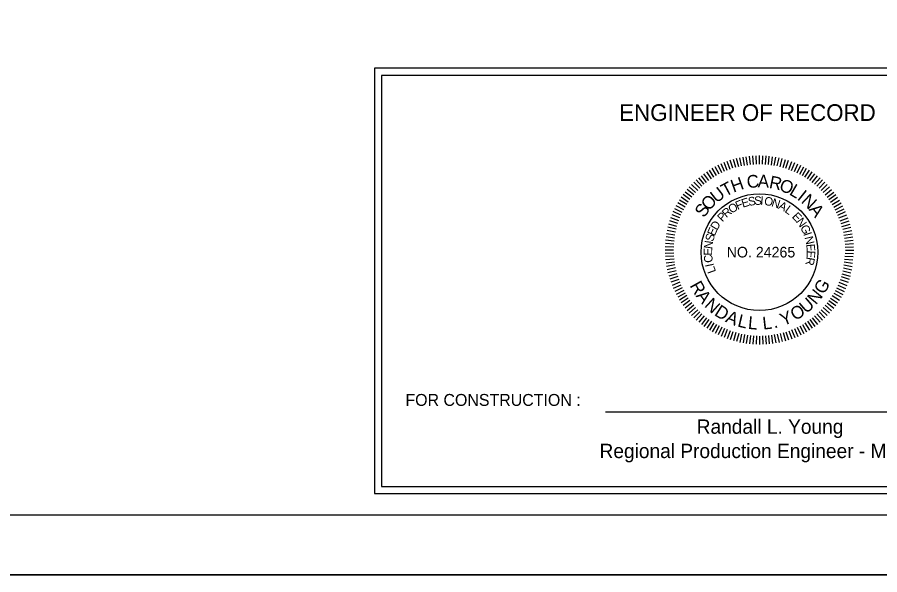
# Model space of a CAD drawing. Extents: x -796 to 2793, y -4650 to 4425.
# Drawn here: x 2234 to 2596, y 1000 to 1233.8 of the extents above; entities that cross this region are included whole.
import ezdxf

# ---------------------------------------------------------------- set-up
doc = ezdxf.new("R2010")
doc.units = 0
for name, color, linetype in [('RD_EX_Misc', 7, 'Continuous'), ('RD_HC_CL', 7, 'Continuous'), ('RD_HC_Data', 7, 'Continuous'), ('RD_HC_Data_Tic', 7, 'Continuous'), ('RD_SHT_Bndy', 7, 'Continuous')]:
    doc.layers.add(name, color=color, linetype=linetype)

msp = doc.modelspace()

# ---------------------------------------------------------------- linework, layer by layer
at = {"layer": 'RD_EX_Misc'}
for p, q in [((2531.98, 1169.54), (2530.65, 1172.84)), ((2531.98, 1169.54), (2530.65, 1172.84)), ((2533.16, 1169.99), (2531.94, 1173.33)), ((2533.16, 1169.99), (2531.94, 1173.33)), ((2534.33, 1170.44), (2533.23, 1173.83)), ((2534.33, 1170.44), (2533.23, 1173.83)), ((2535.55, 1170.77), (2534.57, 1174.18)), ((2535.55, 1170.77), (2534.57, 1174.18)), ((2536.76, 1171.09), (2535.9, 1174.54)), ((2536.76, 1171.09), (2535.9, 1174.54)), ((2537.98, 1171.42), (2537.24, 1174.9)), ((2537.98, 1171.42), (2537.24, 1174.9)), ((2539.22, 1171.61), (2538.6, 1175.12)), ((2539.22, 1171.61), (2538.6, 1175.12)), ((2540.46, 1171.81), (2539.97, 1175.33)), ((2540.46, 1171.81), (2539.97, 1175.33)), ((2541.7, 1172.01), (2541.33, 1175.55)), ((2541.7, 1172.01), (2541.33, 1175.55)), ((2542.96, 1172.07), (2542.71, 1175.62)), ((2542.96, 1172.07), (2542.71, 1175.62)), ((2544.21, 1172.14), (2544.09, 1175.69)), ((2544.21, 1172.14), (2544.09, 1175.69)), ((2545.47, 1172.2), (2545.47, 1175.76)), ((2545.47, 1172.2), (2545.47, 1175.76)), ((2546.73, 1172.14), (2546.85, 1175.69)), ((2546.73, 1172.14), (2546.85, 1175.69)), ((2547.98, 1172.07), (2548.23, 1175.62)), ((2547.98, 1172.07), (2548.23, 1175.62)), ((2549.24, 1172.01), (2549.61, 1175.55)), ((2549.24, 1172.01), (2549.61, 1175.55)), ((2550.48, 1171.81), (2550.98, 1175.33)), ((2550.48, 1171.81), (2550.98, 1175.33)), ((2551.72, 1171.61), (2552.34, 1175.12)), ((2551.72, 1171.61), (2552.34, 1175.12)), ((2552.96, 1171.42), (2553.71, 1174.9)), ((2552.96, 1171.42), (2553.71, 1174.9)), ((2552.96, 1171.42), (2553.71, 1174.9)), ((2554.18, 1171.09), (2555.04, 1174.54)), ((2554.18, 1171.09), (2555.04, 1174.54)), ((2554.18, 1171.09), (2555.04, 1174.54)), ((2555.39, 1170.77), (2556.37, 1174.18)), ((2555.39, 1170.77), (2556.37, 1174.18)), ((2555.39, 1170.77), (2556.37, 1174.18)), ((2556.61, 1170.44), (2557.71, 1173.83)), ((2556.61, 1170.44), (2557.71, 1173.83)), ((2556.61, 1170.44), (2557.71, 1173.83)), ((2557.78, 1169.99), (2559, 1173.33)), ((2557.78, 1169.99), (2559, 1173.33)), ((2557.78, 1169.99), (2559, 1173.33)), ((2558.96, 1169.54), (2560.29, 1172.84)), ((2558.96, 1169.54), (2560.29, 1172.84)), ((2558.96, 1169.54), (2560.29, 1172.84)), ((2526.39, 1166.69), (2524.51, 1169.71)), ((2526.39, 1166.69), (2524.51, 1169.71)), ((2527.45, 1167.38), (2525.67, 1170.46)), ((2527.45, 1167.38), (2525.67, 1170.46)), ((2528.57, 1167.95), (2526.9, 1171.09)), ((2528.57, 1167.95), (2526.9, 1171.09)), ((2529.69, 1168.52), (2528.13, 1171.71)), ((2529.69, 1168.52), (2528.13, 1171.71)), ((2530.81, 1169.09), (2529.36, 1172.34)), ((2530.81, 1169.09), (2529.36, 1172.34)), ((2560.13, 1169.09), (2561.58, 1172.34)), ((2560.13, 1169.09), (2561.58, 1172.34)), ((2560.13, 1169.09), (2561.58, 1172.34)), ((2561.25, 1168.52), (2562.81, 1171.71)), ((2561.25, 1168.52), (2562.81, 1171.71)), ((2561.25, 1168.52), (2562.81, 1171.71)), ((2562.37, 1167.95), (2564.04, 1171.09)), ((2562.37, 1167.95), (2564.04, 1171.09)), ((2562.37, 1167.95), (2564.04, 1171.09)), ((2563.49, 1167.38), (2565.27, 1170.46)), ((2563.49, 1167.38), (2565.27, 1170.46)), ((2563.49, 1167.38), (2565.27, 1170.46)), ((2564.55, 1166.69), (2566.43, 1169.71)), ((2564.55, 1166.69), (2566.43, 1169.71)), ((2564.55, 1166.69), (2566.43, 1169.71)), ((2521.35, 1162.95), (2518.97, 1165.59)), ((2521.35, 1162.95), (2518.97, 1165.59)), ((2522.33, 1163.74), (2520.04, 1166.46)), ((2522.33, 1163.74), (2520.04, 1166.46)), ((2523.31, 1164.53), (2521.12, 1167.33)), ((2523.31, 1164.53), (2521.12, 1167.33)), ((2524.28, 1165.32), (2522.19, 1168.2)), ((2524.28, 1165.32), (2522.19, 1168.2)), ((2525.34, 1166.01), (2523.35, 1168.95)), ((2525.34, 1166.01), (2523.35, 1168.95)), ((2565.6, 1166.01), (2567.59, 1168.95)), ((2565.6, 1166.01), (2567.59, 1168.95)), ((2565.6, 1166.01), (2567.59, 1168.95)), ((2566.66, 1165.32), (2568.75, 1168.2)), ((2566.66, 1165.32), (2568.75, 1168.2)), ((2566.66, 1165.32), (2568.75, 1168.2)), ((2567.64, 1164.53), (2569.82, 1167.33)), ((2567.64, 1164.53), (2569.82, 1167.33)), ((2567.64, 1164.53), (2569.82, 1167.33)), ((2568.61, 1163.74), (2570.9, 1166.46)), ((2568.61, 1163.74), (2570.9, 1166.46)), ((2568.61, 1163.74), (2570.9, 1166.46)), ((2569.59, 1162.95), (2571.97, 1165.59)), ((2569.59, 1162.95), (2571.97, 1165.59)), ((2569.59, 1162.95), (2571.97, 1165.59)), ((2518.68, 1160.28), (2516.04, 1162.66)), ((2518.68, 1160.28), (2516.04, 1162.66)), ((2519.57, 1161.17), (2517.02, 1163.64)), ((2519.57, 1161.17), (2517.02, 1163.64)), ((2520.46, 1162.06), (2517.99, 1164.61)), ((2520.46, 1162.06), (2517.99, 1164.61)), ((2570.48, 1162.06), (2572.95, 1164.61)), ((2570.48, 1162.06), (2572.95, 1164.61)), ((2570.48, 1162.06), (2572.95, 1164.61)), ((2571.37, 1161.17), (2573.93, 1163.64)), ((2571.37, 1161.17), (2573.93, 1163.64)), ((2571.37, 1161.17), (2573.93, 1163.64)), ((2572.26, 1160.28), (2574.9, 1162.66)), ((2572.26, 1160.28), (2574.9, 1162.66)), ((2572.26, 1160.28), (2574.9, 1162.66)), ((2515.62, 1156.29), (2512.68, 1158.28)), ((2515.62, 1156.29), (2512.68, 1158.28)), ((2516.31, 1157.35), (2513.43, 1159.44)), ((2516.31, 1157.35), (2513.43, 1159.44)), ((2517.1, 1158.32), (2514.3, 1160.51)), ((2517.1, 1158.32), (2514.3, 1160.51)), ((2517.89, 1159.3), (2515.17, 1161.59)), ((2517.89, 1159.3), (2515.17, 1161.59)), ((2573.05, 1159.3), (2575.77, 1161.59)), ((2573.05, 1159.3), (2575.77, 1161.59)), ((2573.05, 1159.3), (2575.77, 1161.59)), ((2573.84, 1158.32), (2576.64, 1160.51)), ((2573.84, 1158.32), (2576.64, 1160.51)), ((2573.84, 1158.32), (2576.64, 1160.51)), ((2574.63, 1157.35), (2577.51, 1159.44)), ((2574.63, 1157.35), (2577.51, 1159.44)), ((2574.63, 1157.35), (2577.51, 1159.44)), ((2575.32, 1156.29), (2578.26, 1158.28)), ((2575.32, 1156.29), (2578.26, 1158.28)), ((2575.32, 1156.29), (2578.26, 1158.28)), ((2513.68, 1153.06), (2510.54, 1154.73)), ((2513.68, 1153.06), (2510.54, 1154.73)), ((2514.25, 1154.18), (2511.17, 1155.96)), ((2514.25, 1154.18), (2511.17, 1155.96)), ((2514.94, 1155.24), (2511.92, 1157.12)), ((2514.94, 1155.24), (2511.92, 1157.12)), ((2576, 1155.24), (2579.02, 1157.12)), ((2576, 1155.24), (2579.02, 1157.12)), ((2576, 1155.24), (2579.02, 1157.12)), ((2576.69, 1154.18), (2579.77, 1155.96)), ((2576.69, 1154.18), (2579.77, 1155.96)), ((2576.69, 1154.18), (2579.77, 1155.96)), ((2577.26, 1153.06), (2580.4, 1154.73)), ((2577.26, 1153.06), (2580.4, 1154.73)), ((2577.26, 1153.06), (2580.4, 1154.73)), ((2512.54, 1150.82), (2509.29, 1152.27)), ((2512.54, 1150.82), (2509.29, 1152.27)), ((2513.11, 1151.94), (2509.92, 1153.5)), ((2513.11, 1151.94), (2509.92, 1153.5)), ((2577.83, 1151.94), (2581.02, 1153.5)), ((2577.83, 1151.94), (2581.02, 1153.5)), ((2577.83, 1151.94), (2581.02, 1153.5)), ((2578.4, 1150.82), (2581.65, 1152.27)), ((2578.4, 1150.82), (2581.65, 1152.27)), ((2578.4, 1150.82), (2581.65, 1152.27)), ((2511.19, 1147.3), (2507.8, 1148.4)), ((2511.19, 1147.3), (2507.8, 1148.4)), ((2511.64, 1148.47), (2508.3, 1149.69)), ((2511.64, 1148.47), (2508.3, 1149.69)), ((2512.09, 1149.65), (2508.79, 1150.98)), ((2512.09, 1149.65), (2508.79, 1150.98)), ((2578.85, 1149.65), (2582.15, 1150.98)), ((2578.85, 1149.65), (2582.15, 1150.98)), ((2578.85, 1149.65), (2582.15, 1150.98)), ((2579.3, 1148.47), (2582.64, 1149.69)), ((2579.3, 1148.47), (2582.64, 1149.69)), ((2579.3, 1148.47), (2582.64, 1149.69)), ((2579.75, 1147.3), (2583.14, 1148.4)), ((2579.75, 1147.3), (2583.14, 1148.4)), ((2579.75, 1147.3), (2583.14, 1148.4)), ((2510.21, 1143.65), (2506.73, 1144.39)), ((2510.21, 1143.65), (2506.73, 1144.39)), ((2510.54, 1144.87), (2507.09, 1145.73)), ((2510.54, 1144.87), (2507.09, 1145.73)), ((2510.86, 1146.08), (2507.45, 1147.06)), ((2510.86, 1146.08), (2507.45, 1147.06)), ((2580.08, 1146.08), (2583.5, 1147.06)), ((2580.08, 1146.08), (2583.5, 1147.06)), ((2580.08, 1146.08), (2583.5, 1147.06)), ((2580.4, 1144.87), (2583.85, 1145.73)), ((2580.4, 1144.87), (2583.85, 1145.73)), ((2580.4, 1144.87), (2583.85, 1145.73)), ((2580.73, 1143.65), (2584.21, 1144.39)), ((2580.73, 1143.65), (2584.21, 1144.39)), ((2580.73, 1143.65), (2584.21, 1144.39)), ((2509.62, 1139.93), (2506.08, 1140.3)), ((2509.62, 1139.93), (2506.08, 1140.3)), ((2509.82, 1141.17), (2506.3, 1141.67)), ((2509.82, 1141.17), (2506.3, 1141.67)), ((2510.02, 1142.41), (2506.52, 1143.03)), ((2510.02, 1142.41), (2506.52, 1143.03)), ((2580.92, 1142.41), (2584.43, 1143.03)), ((2580.92, 1142.41), (2584.43, 1143.03)), ((2580.92, 1142.41), (2584.43, 1143.03)), ((2581.12, 1141.17), (2584.64, 1141.67)), ((2581.12, 1141.17), (2584.64, 1141.67)), ((2581.12, 1141.17), (2584.64, 1141.67)), ((2581.32, 1139.93), (2584.86, 1140.3)), ((2581.32, 1139.93), (2584.86, 1140.3)), ((2581.32, 1139.93), (2584.86, 1140.3)), ((2509.49, 1137.42), (2505.94, 1137.54)), ((2509.49, 1137.42), (2505.94, 1137.54)), ((2509.56, 1138.67), (2506.01, 1138.92)), ((2509.56, 1138.67), (2506.01, 1138.92)), ((2581.38, 1138.67), (2584.93, 1138.92)), ((2581.38, 1138.67), (2584.93, 1138.92)), ((2581.38, 1138.67), (2584.93, 1138.92)), ((2581.45, 1137.42), (2585, 1137.54)), ((2581.45, 1137.42), (2585, 1137.54)), ((2581.45, 1137.42), (2585, 1137.54)), ((2509.43, 1136.16), (2505.87, 1136.16)), ((2509.43, 1136.16), (2505.87, 1136.16)), ((2509.49, 1134.9), (2505.94, 1134.78)), ((2509.49, 1134.9), (2505.94, 1134.78)), ((2509.56, 1133.65), (2506.01, 1133.4)), ((2509.56, 1133.65), (2506.01, 1133.4)), ((2581.25, 1133.66), (2584.79, 1133.41)), ((2581.25, 1133.66), (2584.79, 1133.41)), ((2581.38, 1134.91), (2584.93, 1134.78)), ((2581.38, 1134.91), (2584.93, 1134.78)), ((2581.52, 1136.16), (2585.08, 1136.16)), ((2581.52, 1136.16), (2585.08, 1136.16)), ((2581.52, 1136.16), (2585.08, 1136.16)), ((2509.62, 1132.39), (2506.08, 1132.02)), ((2509.62, 1132.39), (2506.08, 1132.02)), ((2509.82, 1131.15), (2506.3, 1130.65)), ((2509.82, 1131.15), (2506.3, 1130.65)), ((2510.02, 1129.91), (2506.52, 1129.29)), ((2510.02, 1129.91), (2506.52, 1129.29)), ((2580.86, 1129.92), (2584.36, 1129.3)), ((2580.86, 1129.92), (2584.36, 1129.3)), ((2580.99, 1131.17), (2584.5, 1130.67)), ((2580.99, 1131.17), (2584.5, 1130.67)), ((2581.12, 1132.41), (2584.64, 1132.04)), ((2581.12, 1132.41), (2584.64, 1132.04)), ((2510.21, 1128.67), (2506.73, 1127.93)), ((2510.21, 1128.67), (2506.73, 1127.93)), ((2510.54, 1127.45), (2507.09, 1126.59)), ((2510.54, 1127.45), (2507.09, 1126.59)), ((2510.86, 1126.24), (2507.45, 1125.26)), ((2510.86, 1126.24), (2507.45, 1125.26)), ((2580.08, 1126.24), (2583.5, 1125.26)), ((2580.08, 1126.24), (2583.5, 1125.26)), ((2580.4, 1127.45), (2583.85, 1126.59)), ((2580.4, 1127.45), (2583.85, 1126.59)), ((2580.73, 1128.67), (2584.21, 1127.93)), ((2580.73, 1128.67), (2584.21, 1127.93)), ((2511.19, 1125.02), (2507.8, 1123.92)), ((2511.64, 1123.85), (2508.3, 1122.63)), ((2511.64, 1123.85), (2508.3, 1122.63)), ((2512.09, 1122.67), (2508.79, 1121.34)), ((2512.09, 1122.67), (2508.79, 1121.34)), ((2578.85, 1122.67), (2582.15, 1121.34)), ((2578.85, 1122.67), (2582.15, 1121.34)), ((2579.3, 1123.85), (2582.64, 1122.63)), ((2579.3, 1123.85), (2582.64, 1122.63)), ((2579.75, 1125.02), (2583.14, 1123.92)), ((2579.75, 1125.02), (2583.14, 1123.92)), ((2512.54, 1121.5), (2509.29, 1120.05)), ((2512.54, 1121.5), (2509.29, 1120.05)), ((2513.11, 1120.38), (2509.92, 1118.82)), ((2513.11, 1120.38), (2509.92, 1118.82)), ((2513.68, 1119.26), (2510.54, 1117.59)), ((2513.68, 1119.26), (2510.54, 1117.59)), ((2577.26, 1119.26), (2580.4, 1117.59)), ((2577.26, 1119.26), (2580.4, 1117.59)), ((2577.83, 1120.38), (2581.02, 1118.82)), ((2577.83, 1120.38), (2581.02, 1118.82)), ((2578.4, 1121.5), (2581.65, 1120.05)), ((2578.4, 1121.5), (2581.65, 1120.05)), ((2514.25, 1118.14), (2511.17, 1116.36)), ((2514.25, 1118.14), (2511.17, 1116.36)), ((2514.94, 1117.08), (2511.92, 1115.2)), ((2514.94, 1117.08), (2511.92, 1115.2)), ((2515.62, 1116.03), (2512.68, 1114.04)), ((2515.62, 1116.03), (2512.68, 1114.04)), ((2516.31, 1114.97), (2513.43, 1112.88)), ((2516.31, 1114.97), (2513.43, 1112.88)), ((2574.63, 1114.97), (2577.51, 1112.88)), ((2574.63, 1114.97), (2577.51, 1112.88)), ((2575.32, 1116.03), (2578.26, 1114.04)), ((2575.32, 1116.03), (2578.26, 1114.04)), ((2576, 1117.08), (2579.02, 1115.2)), ((2576, 1117.08), (2579.02, 1115.2)), ((2576.69, 1118.14), (2579.77, 1116.36)), ((2576.69, 1118.14), (2579.77, 1116.36)), ((2517.1, 1114), (2514.3, 1111.81)), ((2517.1, 1114), (2514.3, 1111.81)), ((2517.89, 1113.02), (2515.17, 1110.73)), ((2517.89, 1113.02), (2515.17, 1110.73)), ((2518.68, 1112.04), (2516.04, 1109.66)), ((2518.68, 1112.04), (2516.04, 1109.66)), ((2572.26, 1112.04), (2574.9, 1109.66)), ((2572.26, 1112.04), (2574.9, 1109.66)), ((2573.05, 1113.02), (2575.77, 1110.73)), ((2573.05, 1113.02), (2575.77, 1110.73)), ((2573.84, 1114), (2576.64, 1111.81)), ((2573.84, 1114), (2576.64, 1111.81)), ((2519.57, 1111.15), (2517.02, 1108.68)), ((2519.57, 1111.15), (2517.02, 1108.68)), ((2520.46, 1110.26), (2517.99, 1107.71)), ((2520.46, 1110.26), (2517.99, 1107.71)), ((2521.35, 1109.37), (2518.97, 1106.73)), ((2521.35, 1109.37), (2518.97, 1106.73)), ((2522.33, 1108.58), (2520.04, 1105.86)), ((2522.33, 1108.58), (2520.04, 1105.86)), ((2523.31, 1107.79), (2521.12, 1104.99)), ((2523.31, 1107.79), (2521.12, 1104.99)), ((2567.64, 1107.79), (2569.82, 1104.99)), ((2567.64, 1107.79), (2569.82, 1104.99)), ((2568.61, 1108.58), (2570.9, 1105.86)), ((2568.61, 1108.58), (2570.9, 1105.86)), ((2569.59, 1109.37), (2571.97, 1106.73)), ((2570.48, 1110.26), (2572.95, 1107.71)), ((2570.48, 1110.26), (2572.95, 1107.71)), ((2571.37, 1111.15), (2573.93, 1108.68)), ((2571.37, 1111.15), (2573.93, 1108.68)), ((2524.28, 1107), (2522.19, 1104.12)), ((2524.28, 1107), (2522.19, 1104.12)), ((2525.34, 1106.31), (2523.35, 1103.37)), ((2525.34, 1106.31), (2523.35, 1103.37)), ((2526.39, 1105.63), (2524.51, 1102.61)), ((2526.39, 1105.63), (2524.51, 1102.61)), ((2527.45, 1104.94), (2525.67, 1101.86)), ((2527.45, 1104.94), (2525.67, 1101.86)), ((2528.57, 1104.37), (2526.9, 1101.23)), ((2528.57, 1104.37), (2526.9, 1101.23)), ((2562.37, 1104.37), (2564.04, 1101.23)), ((2562.37, 1104.37), (2564.04, 1101.23)), ((2563.49, 1104.94), (2565.27, 1101.86)), ((2563.49, 1104.94), (2565.27, 1101.86)), ((2564.55, 1105.63), (2566.43, 1102.61)), ((2564.55, 1105.63), (2566.43, 1102.61)), ((2565.6, 1106.31), (2567.59, 1103.37)), ((2565.6, 1106.31), (2567.59, 1103.37)), ((2566.66, 1107), (2568.75, 1104.12)), ((2566.66, 1107), (2568.75, 1104.12)), ((2529.69, 1103.8), (2528.13, 1100.61)), ((2529.69, 1103.8), (2528.13, 1100.61)), ((2530.81, 1103.23), (2529.36, 1099.98)), ((2530.81, 1103.23), (2529.36, 1099.98)), ((2531.98, 1102.78), (2530.65, 1099.48)), ((2531.98, 1102.78), (2530.65, 1099.48)), ((2533.16, 1102.33), (2531.94, 1098.99)), ((2533.16, 1102.33), (2531.94, 1098.99)), ((2534.33, 1101.88), (2533.23, 1098.49)), ((2534.33, 1101.88), (2533.23, 1098.49)), ((2535.55, 1101.55), (2534.57, 1098.14)), ((2535.55, 1101.55), (2534.57, 1098.14)), ((2536.76, 1101.23), (2535.9, 1097.78)), ((2536.76, 1101.23), (2535.9, 1097.78)), ((2537.98, 1100.9), (2537.24, 1097.42)), ((2537.98, 1100.9), (2537.24, 1097.42)), ((2539.22, 1100.71), (2538.6, 1097.2)), ((2539.22, 1100.71), (2538.6, 1097.2)), ((2540.46, 1100.51), (2539.97, 1096.99)), ((2540.46, 1100.51), (2539.97, 1096.99)), ((2550.48, 1100.51), (2550.98, 1096.99)), ((2550.48, 1100.51), (2550.98, 1096.99)), ((2551.72, 1100.71), (2552.34, 1097.2)), ((2551.72, 1100.71), (2552.34, 1097.2)), ((2552.96, 1100.9), (2553.71, 1097.42)), ((2552.96, 1100.9), (2553.71, 1097.42)), ((2554.18, 1101.23), (2555.04, 1097.78)), ((2554.18, 1101.23), (2555.04, 1097.78)), ((2555.39, 1101.55), (2556.37, 1098.14)), ((2555.39, 1101.55), (2556.37, 1098.14)), ((2556.61, 1101.88), (2557.71, 1098.49)), ((2556.61, 1101.88), (2557.71, 1098.49)), ((2557.78, 1102.33), (2559, 1098.99)), ((2557.78, 1102.33), (2559, 1098.99)), ((2558.96, 1102.78), (2560.29, 1099.48)), ((2558.96, 1102.78), (2560.29, 1099.48)), ((2560.13, 1103.23), (2561.58, 1099.98)), ((2560.13, 1103.23), (2561.58, 1099.98)), ((2561.25, 1103.8), (2562.81, 1100.61)), ((2561.25, 1103.8), (2562.81, 1100.61)), ((2541.7, 1100.31), (2541.33, 1096.77)), ((2541.7, 1100.31), (2541.33, 1096.77)), ((2542.96, 1100.25), (2542.71, 1096.7)), ((2542.96, 1100.25), (2542.71, 1096.7)), ((2544.21, 1100.18), (2544.09, 1096.63)), ((2544.21, 1100.18), (2544.09, 1096.63)), ((2545.47, 1100.11), (2545.47, 1096.55)), ((2545.47, 1100.11), (2545.47, 1096.55)), ((2546.73, 1100.18), (2546.85, 1096.63)), ((2546.73, 1100.18), (2546.85, 1096.63)), ((2547.98, 1100.25), (2548.23, 1096.7)), ((2547.98, 1100.25), (2548.23, 1096.7)), ((2549.24, 1100.31), (2549.61, 1096.77)), ((2549.24, 1100.31), (2549.61, 1096.77))]:
    msp.add_line(p, q, dxfattribs=at)
msp.add_circle((2545.47, 1135.28), 24.48, dxfattribs=at)
at = {"layer": 'RD_HC_CL'}
msp.add_lwpolyline([(984.13, 2100), (2780.13, 2100), (2780.13, 1000), (984.13, 1000)], close=True, dxfattribs=at)
at = {"layer": 'RD_HC_Data'}
for p, q in [((2480.88, 1068.27), (2619.52, 1068.27)), ((2760, 1000), (1000, 1000)), ((1000, 1000), (2759.98, 1000))]:
    msp.add_line(p, q, dxfattribs=at)
for points in [[(1079.63, 2075.05), (2755.13, 2075.05), (2755.13, 1025), (1079.63, 1025)], [(2383.87, 1034.06), (2702.13, 1034.06), (2702.13, 1212.42), (2383.87, 1212.42)], [(2386.87, 1037.06), (2699.13, 1037.06), (2699.13, 1209.42), (2386.87, 1209.42)]]:
    msp.add_lwpolyline(points, close=True, dxfattribs=at)

# ---------------------------------------------------------------- texts
at = {"layer": 'RD_EX_Misc'}
for s, height, rotation, p in [('H', 5.34, 19.9102, (2534.57, 1160.2)), ('C', 5.34, 6.8832, (2540.46, 1162.02)), ('A', 5.34, 357.9448, (2544.68, 1162.47)), ('R', 5.34, 348.267, (2549.26, 1162.22)), ('O', 5.34, 339.3286, (2553.4, 1161.3)), ('U', 5.34, 37.7726, (2527.45, 1155.66)), ('T', 5.34, 28.0947, (2531.13, 1158.4)), ('L', 5.34, 329.6507, (2557.66, 1159.6)), ('O', 5.34, 47.4504, (2524.28, 1152.34)), ('S', 3.56, 8.6909, (2540.96, 1154.67)), ('S', 3.56, 1.79, (2543.32, 1155.07)), ('I', 3.56, 354.889, (2545.71, 1155.19)), ('O', 3.56, 350.4045, (2547.27, 1155.11)), ('I', 5.34, 321.4663, (2561, 1157.62)), ('N', 5.34, 317.0007, (2562.69, 1156.34)), ('S', 5.34, 54.9027, (2522.25, 1149.44)), ('O', 3.56, 31.7869, (2533.72, 1151.35)), ('F', 3.56, 23.0853, (2536.28, 1152.94)), ('E', 3.56, 16.1843, (2538.47, 1153.92)), ('N', 3.56, 341.7029, (2550.25, 1154.61)), ('A', 3.56, 333.0013, (2553.12, 1153.66)), ('L', 3.56, 324.2997, (2555.81, 1152.29)), ('A', 5.34, 307.3229, (2565.99, 1153.14)), ('P', 3.56, 46.7912, (2529.96, 1147.75)), ('R', 3.56, 39.8902, (2531.57, 1149.53)), ('E', 3.56, 313.2251, (2558.88, 1149.99)), ('D', 3.56, 59.074, (2527.66, 1144.17)), ('N', 3.56, 305.7317, (2560.69, 1148.11)), ('E', 3.56, 66.5674, (2526.65, 1141.77)), ('G', 3.56, 297.0301, (2562.45, 1145.66)), ('S', 3.56, 73.4683, (2526.01, 1139.46)), ('I', 3.56, 288.3285, (2563.83, 1142.98)), ('N', 3.56, 283.8441, (2564.38, 1141.52)), ('E', 3.56, 89.6633, (2525.62, 1133.87)), ('N', 3.56, 82.17, (2525.6, 1136.47)), ('E', 3.56, 275.1424, (2565.1, 1138.59)), ('C', 3.56, 97.7667, (2526.01, 1131.08)), ('R', 3.56, 260.1557, (2565.29, 1133.4)), ('E', 3.56, 267.6491, (2565.36, 1136)), ('I', 3.56, 102.2511, (2526.4, 1129.57)), ('L', 3.56, 109.7445, (2527.31, 1127.14)), ('R', 5.34, 299.1493, (2516.07, 1121.31)), ('G', 5.34, 60.1113, (2572.58, 1117.26)), ('A', 5.34, 308.0877, (2518.6, 1116.91)), ('N', 5.34, 50.4335, (2569.16, 1112.96)), ('N', 5.34, 317.7655, (2522.07, 1112.65)), ('U', 5.34, 40.7556, (2565.07, 1109.29)), ('D', 5.34, 327.4433, (2526.2, 1109.04)), ('O', 5.34, 31.0778, (2560.43, 1106.37)), ('A', 5.34, 337.1212, (2530.89, 1106.18)), ('L', 5.34, 346.799, (2535.99, 1104.14)), ('L', 5.34, 354.9835, (2540.52, 1103.11)), ('L', 5.34, 6.5171, (2547.05, 1102.77)), ('Y', 5.34, 21.4, (2555.35, 1104.26)), ('.', 5.34, 14.7016, (2551.67, 1103.32))]:
    msp.add_text(s, height=height, rotation=rotation, dxfattribs=at).set_placement(p)
msp.add_text('NO. 24265', height=4.45, dxfattribs=at).set_placement((2531.72, 1133.06))
at = {"layer": 'RD_HC_Data_Tic'}
for s, height, p in [('ENGINEER OF RECORD', 7, (2486.62, 1190.31)), ('FOR CONSTRUCTION :', 5.0001, (2396.9, 1070.81))]:
    msp.add_text(s, height=height, dxfattribs=at).set_placement(p)
at = {"layer": 'RD_SHT_Bndy'}
for s, p in [('Randall L. Young', (2519.15, 1059.12)), ('Regional Production Engineer - Midlands', (2478.37, 1048.92))]:
    msp.add_text(s, height=6, dxfattribs=at).set_placement(p)

doc.saveas('drawing.dxf')
